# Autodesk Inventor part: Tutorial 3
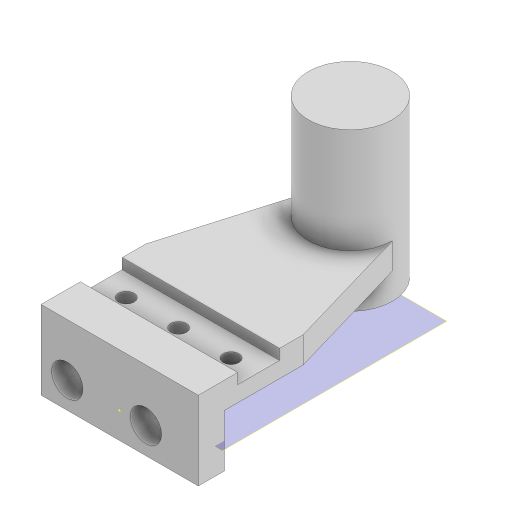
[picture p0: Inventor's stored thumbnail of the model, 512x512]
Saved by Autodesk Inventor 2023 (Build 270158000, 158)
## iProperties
Created: 2021-03
Part Number: Tutorial 3
Material: Generic
Document SubType Name: Modeling
Designer: ASUS Laptop
Density: 1 g/cm^3
Appearance: Default
Author: ASUS Laptop
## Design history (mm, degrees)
sketch "Sketch1"
  geometry: L1 (0, 0)-(30, 0); L2 (30, 0)-(30, -15); L3 (30, -15)-(26, -15); L4 (26, -15)-(26, -31); L5 (26, -31)-(30, -31); L6 (30, -31)-(30, -40); L7 (20, -40)-(20, -10); L8 (20, -10)-(0, -10); L9 (0, -10)-(0, 0); L10 (20, -40)-(30, -40)
  constraints: 20 end point, 8 perpendicular, 1 horizontal, 1 parallel, 1 point on line
  dimensions: "d0" = 16 distance of L3.end L4.end; "d1" = 15 distance of L1.end L2.end; "d2" = 40 distance between parallel lines of L1 L10; "d3" = 30 distance between parallel lines of L9 L2; "d4" = 4 distance between parallel lines of L4 L2; "d5" = 10 distance between parallel lines of L8 L1
extrude "Extrusion1" new body sketch "Sketch1" stored distance "d6" = 60; taper "d7" = 0 deg
sketch "Sketch4"
  geometry: L1 (0, 9)-(60, 9) reference; L2 (0, 9)-(14, 57); L3 (14, 57)-(46, 57); L4 (46, 57)-(60, 9); L5 (60, 9)-(0, 9); L6 (30, -31)-(30, 84.04)
  constraints: 10 end point, 1 collinear, 1 parallel, 1 vertical, 1 other
  dimensions: "d8" = 32 distance of L2.end L3.end; "d9" = 48 distance between parallel lines of L3 L1
extrude "Extrusion2" join sketch "Sketch4" distance "d10" = 10; taper "d11" = 0 deg
workplane "Work Plane1"
sketch "Sketch5"
  geometry: L1 (14, -78)-(46, -78) reference; L2 (0, 0)-(0, 10) reference; C1 r 16 at (30, -78); 1 further point
  constraints: 1 centre point, 1 midpoint
  dimensions: "d13" = 32 diameter of C1; "d14" = 30 distance from line of L2 C1.centre
extrude "Extrusion3" join sketch "Sketch5" distance "d15" = 60; taper "d16" = 0 deg
sketch "Sketch6"
  geometry: L1 (-6.213, 7.5)-(70.808, 7.5); L2 (0, -15)-(60, -15) reference; L3 (0, 0)-(0, 16) reference; C1 r 3 at (10, 7.5); C2 r 3 at (30, 7.5); C3 r 3 at (50, 7.5); 1 further point
  constraints: 3 centre point, 3 point on line, 2 end point, 2 equal radius, 1 horizontal
  dimensions: "d17" = 22.5 distance between parallel lines of L2 L1; "d18" = 10 distance from line of C1.centre L3; "d19" = 20 distance of C2.centre C1.centre; "d20" = 20 distance of C3.centre C2.centre; "d21" = 6 diameter of C1
extrude "Extrusion4" cut sketch "Sketch6" distance "d22" = 60; taper "d23" = 0 deg
sketch "Sketch7"
  geometry: 1 further point
sketch "Sketch8"
  geometry: L1 (10, 10)-(52.331, 10); L2 (0, 0)-(60, 0) reference; L3 (0, 0)-(0, 30) reference; C1 r 6 at (10, 10); C2 r 6 at (40, 10); 1 further point
  constraints: 2 centre point, 2 end point, 1 equal radius, 1 horizontal, 1 point on line
  dimensions: "d24" = 10 distance between parallel lines of L2 L1; "d25" = 10 distance from line of L3 L1.start; "d26" = 30 distance of C2.centre L1.start; "d27" = 12 diameter of C2
extrude "Extrusion5" cut sketch "Sketch8" stored distance "d28" = 10; taper "d29" = 0 deg
body "Solid1"
